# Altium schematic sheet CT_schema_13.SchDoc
size 519 x 434 mm
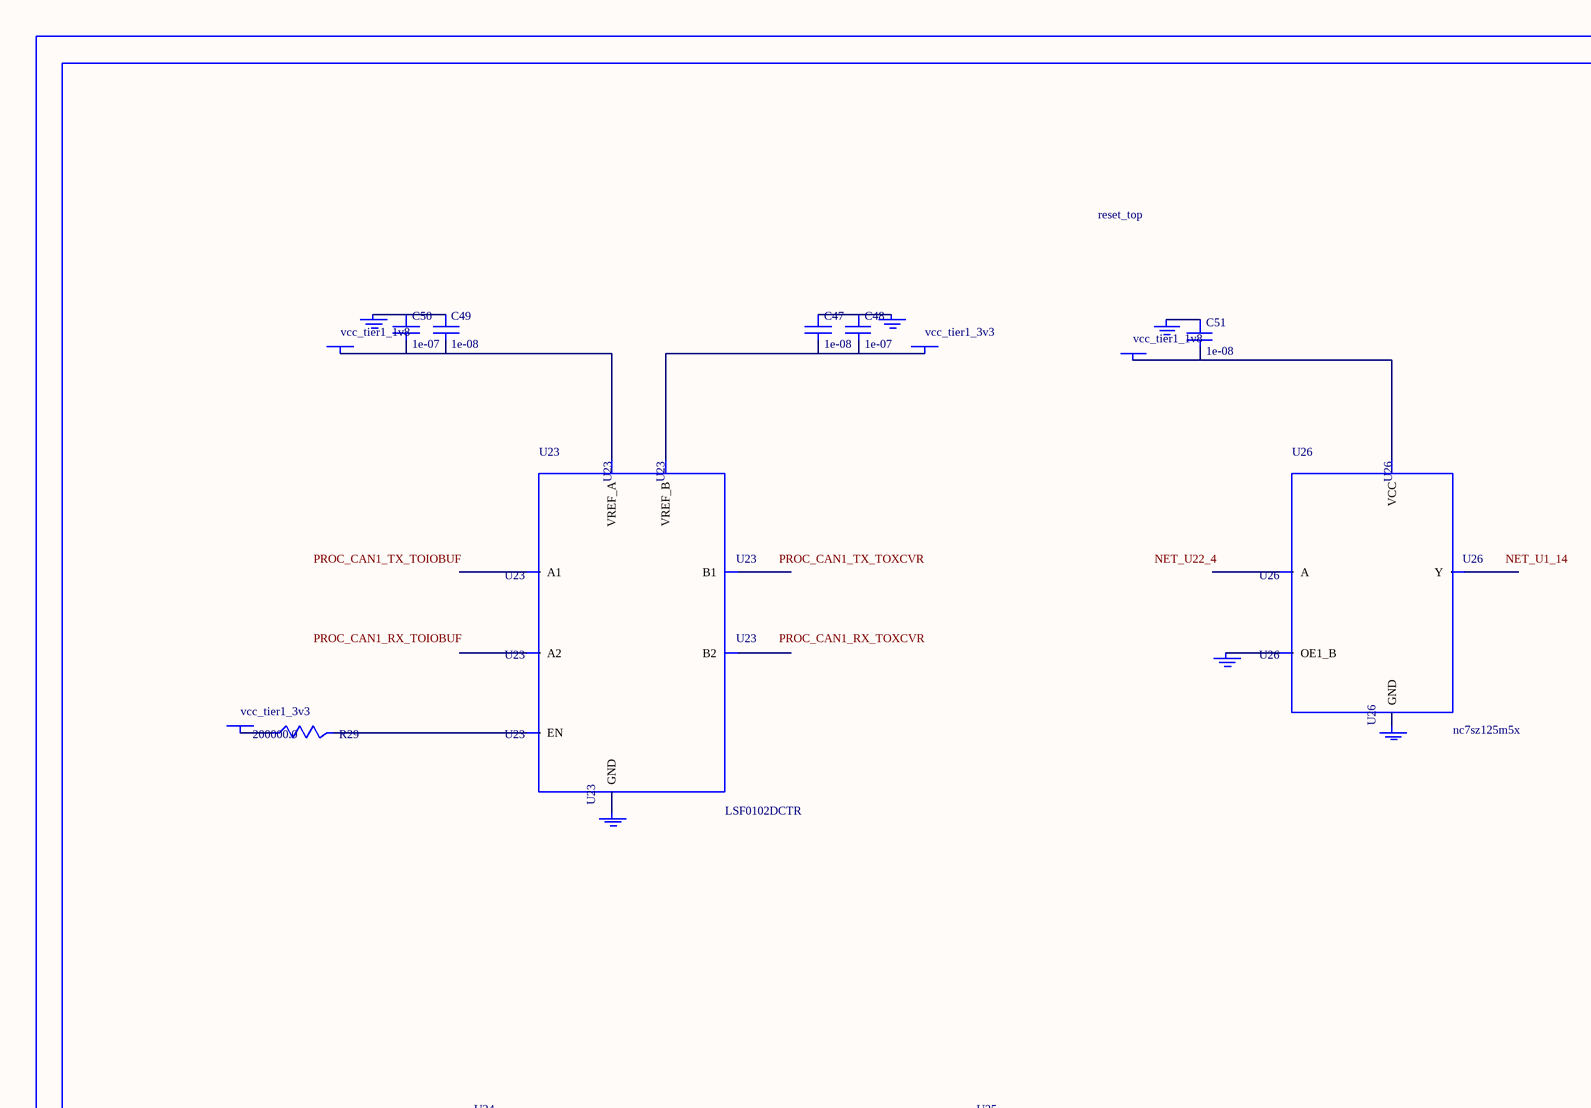
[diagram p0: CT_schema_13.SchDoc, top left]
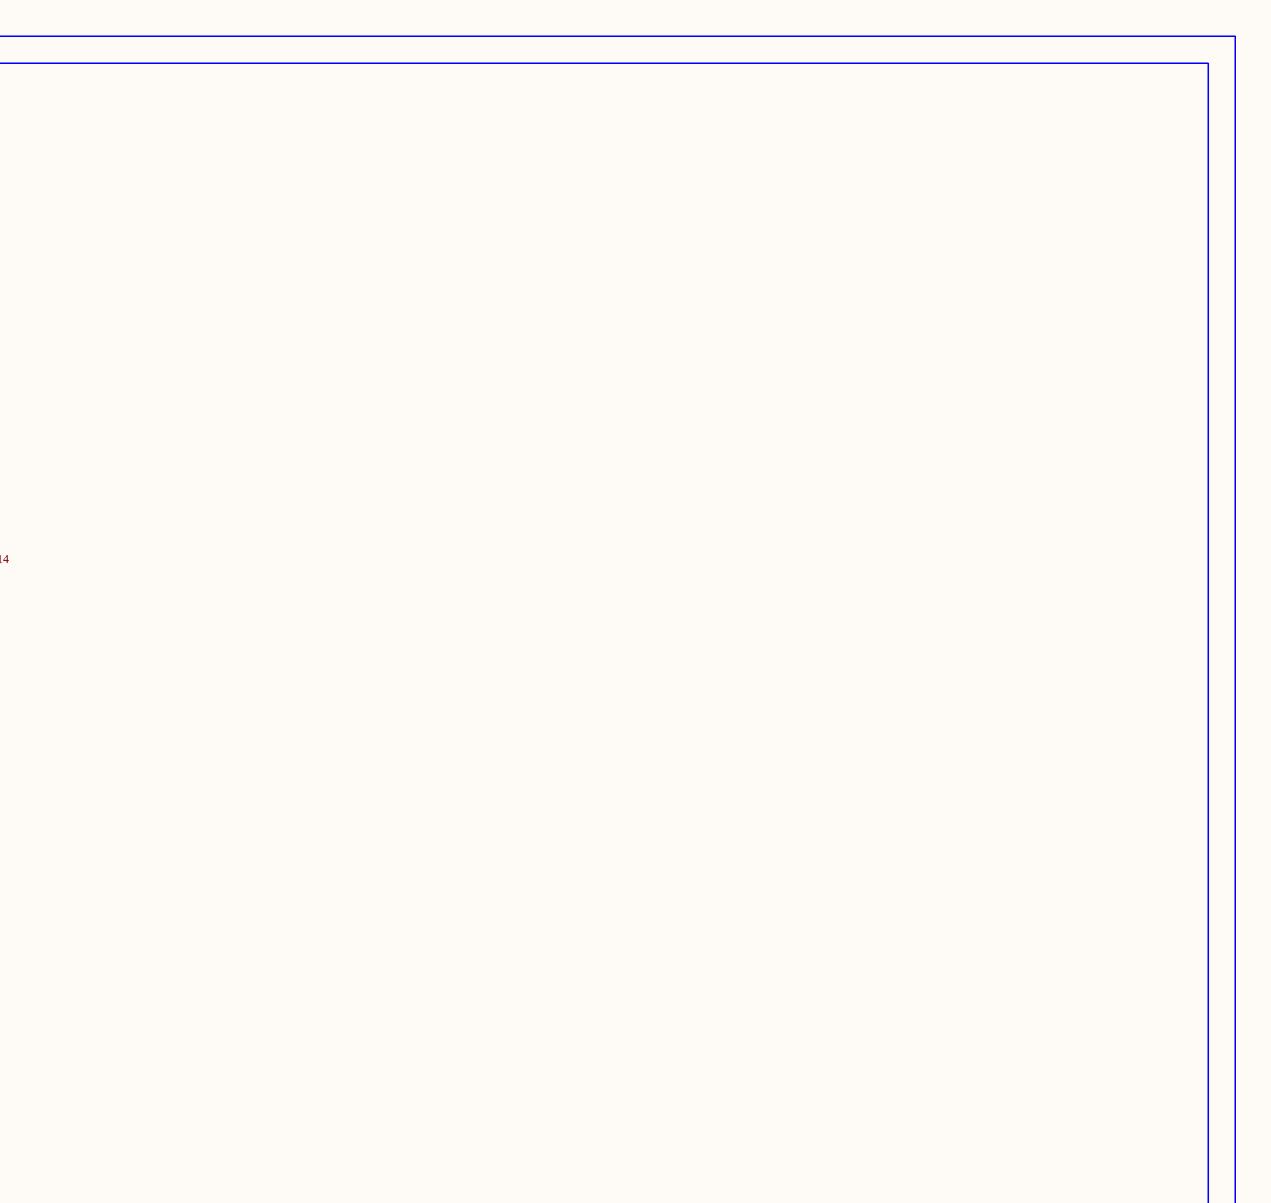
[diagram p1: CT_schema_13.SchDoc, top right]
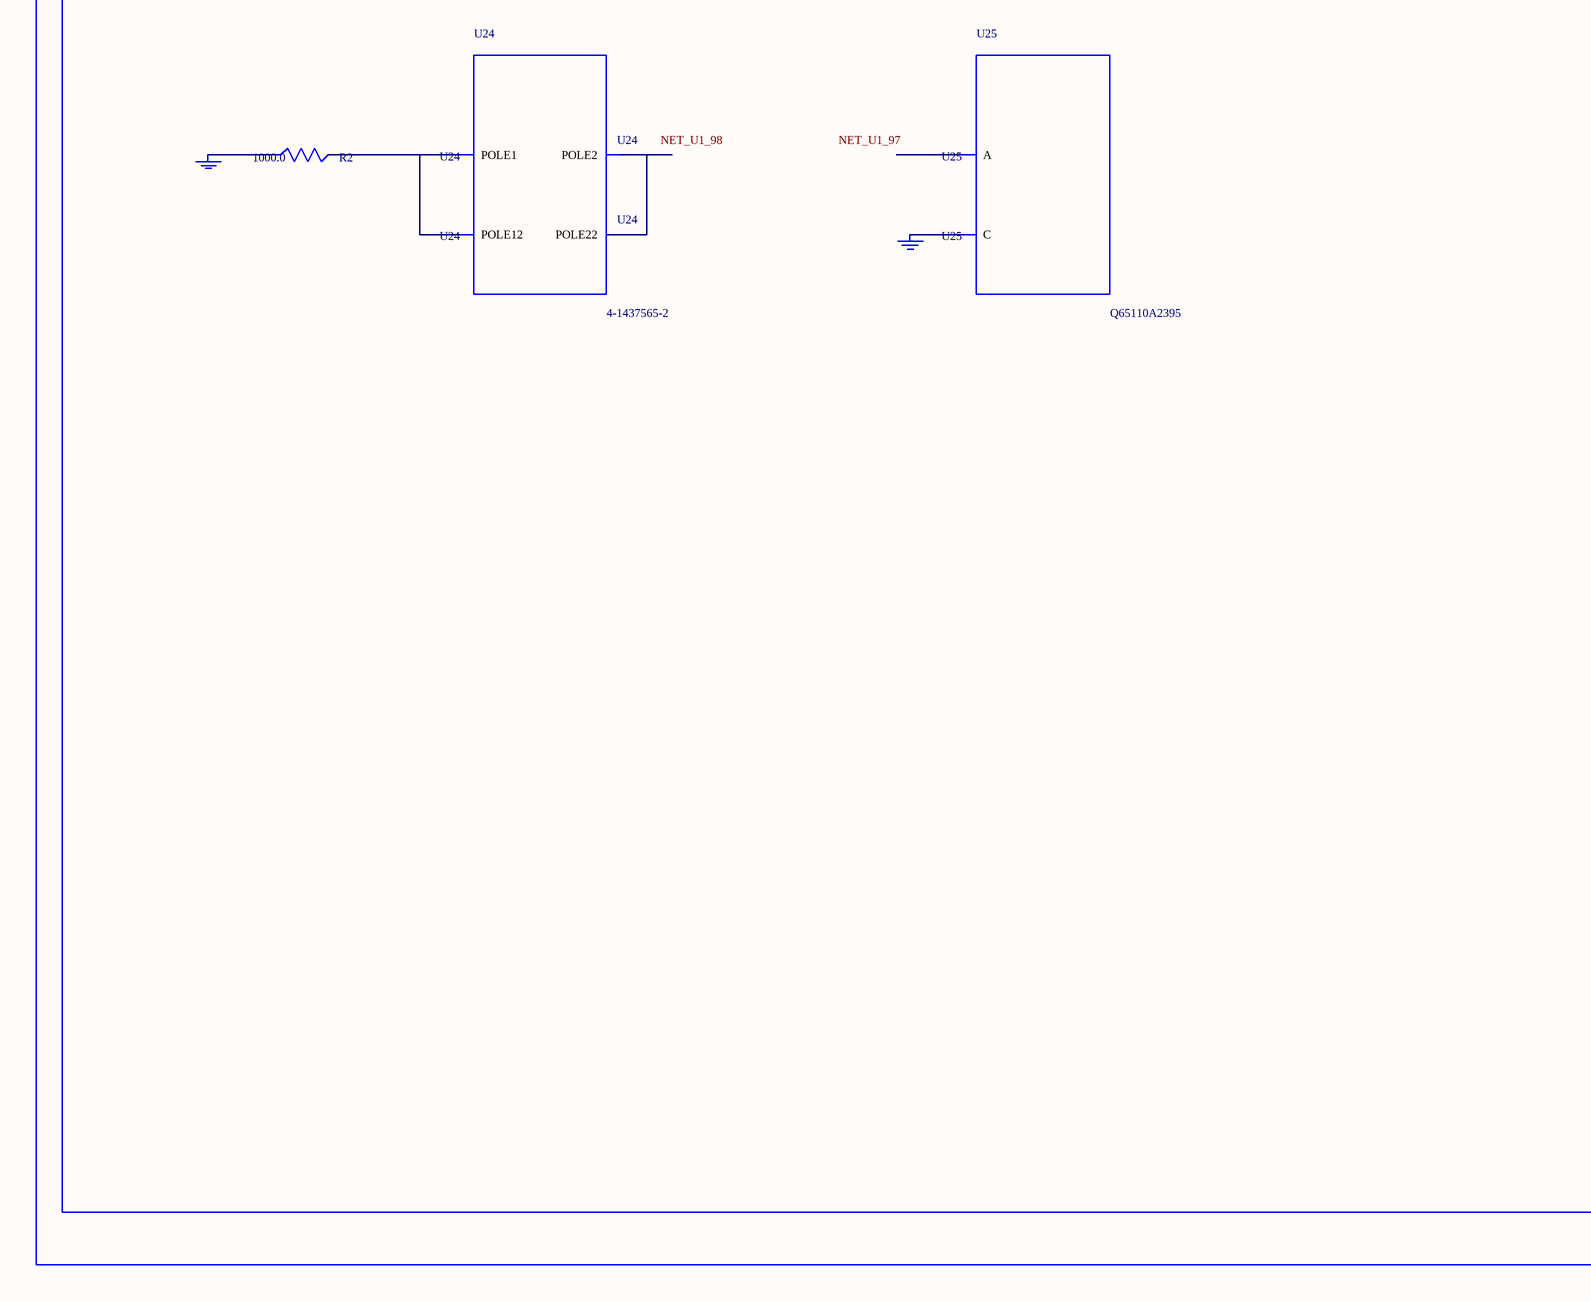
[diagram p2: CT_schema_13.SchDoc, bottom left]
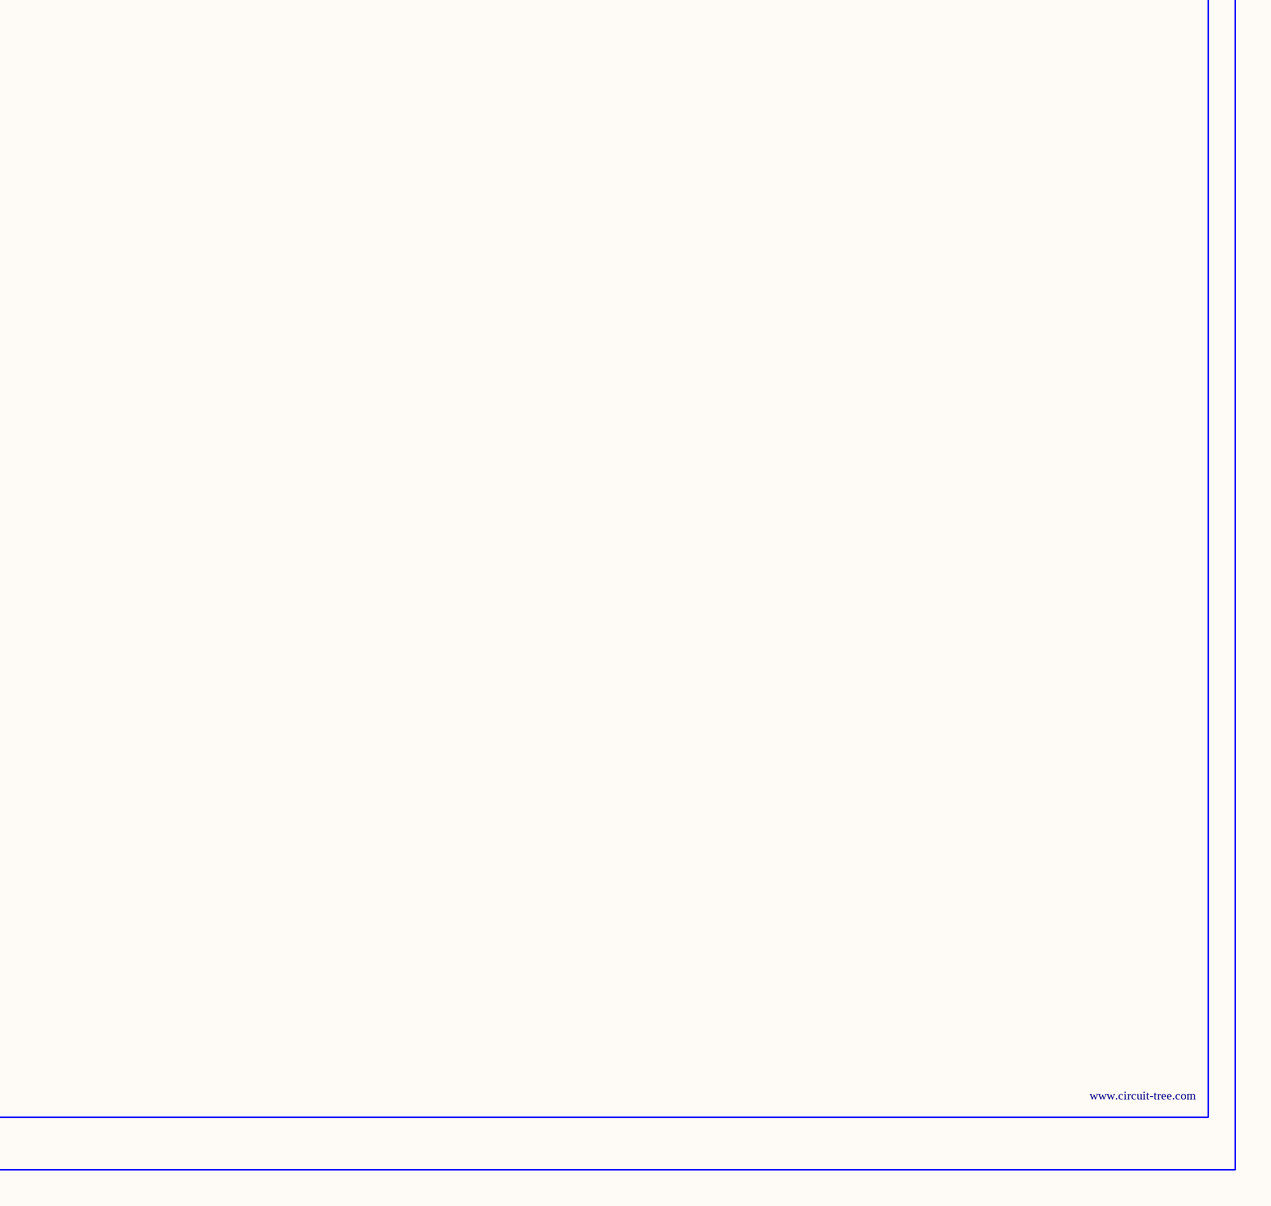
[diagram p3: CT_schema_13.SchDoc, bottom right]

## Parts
BORDER12  (no value)
C47  1e-08  [C0402]
C48  1e-07  [C0402]
C49  1e-08  [C0402]
C50  1e-07  [C0402]
C51  1e-08  [C0402]
GND_INSTANCE_12_0  (no value)
GND_INSTANCE_12_1  (no value)
GND_INSTANCE_12_2  (no value)
GND_INSTANCE_12_3  (no value)
GND_INSTANCE_12_4  (no value)
GND_INSTANCE_12_5  (no value)
GND_INSTANCE_12_6  (no value)
GND_INSTANCE_12_7  (no value)
POWER_INSTANCE_12_0  vcc_tier1_1v8
POWER_INSTANCE_12_1  vcc_tier1_3v3
POWER_INSTANCE_12_2  vcc_tier1_3v3
POWER_INSTANCE_12_3  vcc_tier1_1v8
R2  1000.0  [R0603]
R29  200000.0  [R0603]
U23  LSF0102DCTR  [DCU0008A_N]
U24  4-1437565-2  [SW_4-1437565-2]
U25  Q65110A2395  [LGM67K-G1J2-24-Z]
U26  nc7sz125m5x  [NC7SZ125M5X]

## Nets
NetC47_1: C47.1 C48.1 GND_INSTANCE_12_1.0(GND)
NetC47_2: C47.2 C48.2 POWER_INSTANCE_12_1.0(PWR) U23.7(VREF_B)
NetC49_1: C49.1 C50.1 GND_INSTANCE_12_0.0(GND)
NetC49_2: C49.2 C50.2 POWER_INSTANCE_12_0.0(PWR) U23.2(VREF_A)
NetC51_1: C51.1 GND_INSTANCE_12_5.0(GND)
NetC51_2: C51.2 POWER_INSTANCE_12_3.0(PWR) U26.5(VCC)
NetGND_INSTANCE_12_2_0: GND_INSTANCE_12_2.0(GND) U23.1(GND)
NetGND_INSTANCE_12_3_0: GND_INSTANCE_12_3.0(GND) R2.1
NetGND_INSTANCE_12_4_0: GND_INSTANCE_12_4.0(GND) U25.C
NetGND_INSTANCE_12_6_0: GND_INSTANCE_12_6.0(GND) U26.1(OE1_B)
NetGND_INSTANCE_12_7_0: GND_INSTANCE_12_7.0(GND) U26.3(GND)
NetPOWER_INSTANCE_12_2_0: POWER_INSTANCE_12_2.0(PWR) R29.1
NetR2_2: R2.2 U24.1(POLE1) U24.2(POLE12)
NetR29_2: R29.2 U23.8(EN)
NetU24_3: U24.3(POLE2) U24.4(POLE22)

Not connected (* = marked no-connect by the designer): U23 3(A1) 4(A2) 5(B2) 6(B1); U25 A; U26 2(A) 4(Y)

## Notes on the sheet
- Labels drawn without touching a wire or pin: NET_U1_14, NET_U1_97, NET_U1_98, NET_U22_4, PROC_CAN1_RX_TOIOBUF, PROC_CAN1_RX_TOXCVR, PROC_CAN1_TX_TOIOBUF, PROC_CAN1_TX_TOXCVR

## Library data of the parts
BORDER12 = BORDER_PAGE12
C47 C49 C51 = C0402C103K3RAC
C48 C50 = C0402C104K3RACTU
GND_INSTANCE_12_0-GND_INSTANCE_12_7 = GND
POWER_INSTANCE_12_0-POWER_INSTANCE_12_3 = PWR
R2 = RC0603JR-071KL
R29 = RC0603JR-07200KL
